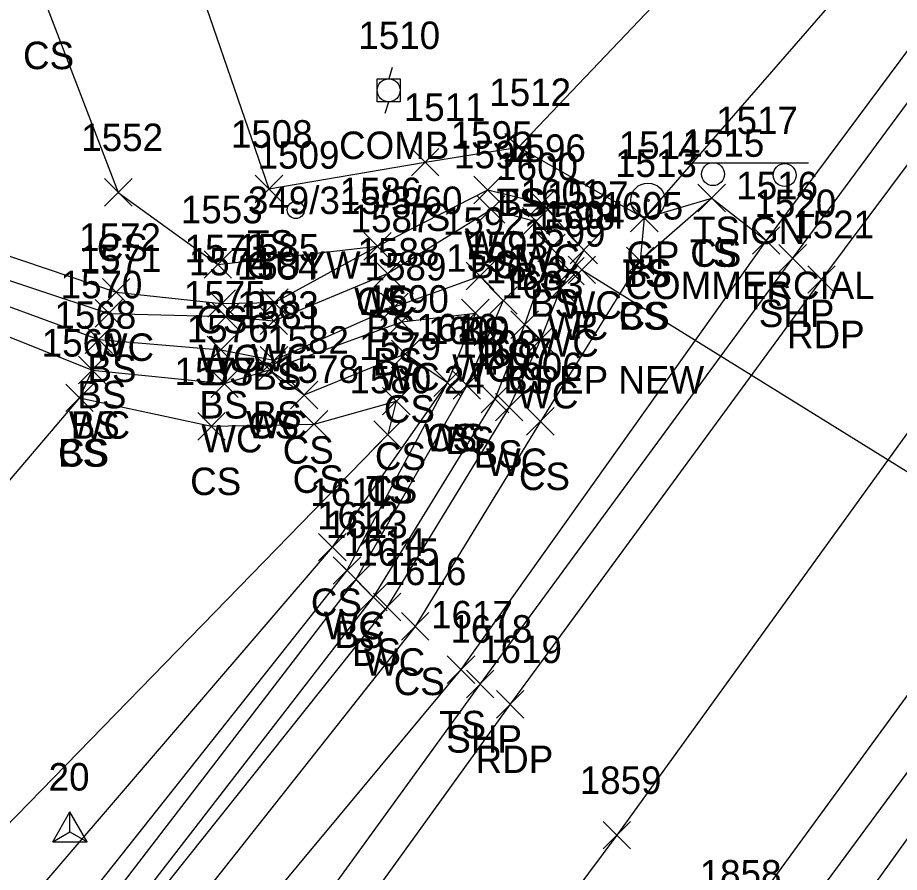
# Model space of a CAD drawing. Extents: x 1520648 to 1523413, y 732854 to 735518.
# Drawn here: x 1522326.3 to 1522390.5, y 734108.7 to 734170.9 of the extents above; entities that cross this region are included whole.
import ezdxf

# ---------------------------------------------------------------- set-up
doc = ezdxf.new("R2010")
doc.units = 0
for name, color, linetype in [('C_I', 7, 'Continuous'), ('CPSM', 7, 'Continuous'), ('D_A', 7, 'Continuous'), ('D_C', 7, 'Continuous'), ('D_I', 7, 'Continuous'), ('D_TIC', 7, 'Continuous'), ('DCP', 7, 'Continuous'), ('L_A', 7, 'Continuous'), ('L_I', 7, 'Continuous'), ('L_TIC', 7, 'Continuous'), ('LAWE', 7, 'Continuous'), ('LELB', 7, 'Continuous'), ('P_A', 7, 'Continuous'), ('P_I', 7, 'Continuous'), ('P_TIC', 7, 'Continuous'), ('PET', 7, 'Continuous'), ('PRC', 7, 'Continuous'), ('PSP', 7, 'Continuous'), ('R_A', 7, 'Continuous'), ('R_I', 7, 'Continuous'), ('RGP', 7, 'Continuous'), ('S_A', 7, 'Continuous'), ('S_C', 7, 'Continuous'), ('S_I', 7, 'Continuous'), ('SSGN', 7, 'Continuous'), ('U_A', 7, 'Continuous'), ('U_C', 7, 'Continuous'), ('U_I', 7, 'Continuous'), ('UP', 7, 'Continuous'), ('UPGW', 7, 'Continuous')]:
    doc.layers.add(name, color=color, linetype=linetype)

msp = doc.modelspace()

# ---------------------------------------------------------------- linework, layer by layer
at = {"layer": 'CPSM'}
for p, q in [((1522328.884, 734110.97), (1522330.134, 734113.135)), ((1522331.384, 734110.97), (1522330.134, 734113.135)), ((1522330.134, 734111.692), (1522330.134, 734113.135)), ((1522328.884, 734110.97), (1522330.134, 734111.692)), ((1522330.134, 734111.692), (1522330.134, 734111.692)), ((1522330.134, 734111.692), (1522331.384, 734110.97)), ((1522328.884, 734110.97), (1522331.384, 734110.97))]:
    msp.add_line(p, q, dxfattribs=at)
at = {"layer": 'D_TIC'}
for points in [[(1522366.367, 734151.564), (1522368.367, 734153.564)], [(1522368.367, 734151.564), (1522366.367, 734153.564)]]:
    msp.add_lwpolyline(points, dxfattribs=at)
at = {"layer": 'DCP'}
msp.add_lwpolyline([(1522367.367, 734152.564), (1522406.62, 734128.212)], dxfattribs=at)
at = {"layer": 'L_TIC'}
for points in [[(1522361.763, 734160.473), (1522363.763, 734162.473)], [(1522363.763, 734160.473), (1522361.763, 734162.473)], [(1522361.763, 734160.473), (1522363.763, 734162.473)], [(1522363.763, 734160.473), (1522361.763, 734162.473)], [(1522354.975, 734159.389), (1522356.975, 734161.389)], [(1522356.975, 734159.389), (1522354.975, 734161.389)], [(1522332.648, 734157.194), (1522334.648, 734159.194)], [(1522334.648, 734157.194), (1522332.648, 734159.194)], [(1522343.612, 734157.443), (1522345.612, 734159.443)], [(1522345.612, 734157.443), (1522343.612, 734159.443)], [(1522359.524, 734157.369), (1522361.524, 734159.369)], [(1522361.524, 734157.369), (1522359.524, 734159.369)], [(1522363.462, 734156.41), (1522365.462, 734158.41)], [(1522365.462, 734156.41), (1522363.462, 734158.41)], [(1522375.814, 734156.779), (1522377.814, 734158.779)], [(1522377.814, 734156.779), (1522375.814, 734158.779)], [(1522375.814, 734156.779), (1522377.814, 734158.779)], [(1522377.814, 734156.779), (1522375.814, 734158.779)], [(1522359.764, 734155.945), (1522361.764, 734157.945)], [(1522361.764, 734155.945), (1522359.764, 734157.945)], [(1522363.042, 734155.082), (1522365.042, 734157.082)], [(1522365.042, 734155.082), (1522363.042, 734157.082)], [(1522370.911, 734155.313), (1522372.911, 734157.313)], [(1522372.911, 734155.313), (1522370.911, 734157.313)], [(1522370.911, 734155.313), (1522372.911, 734157.313)], [(1522372.911, 734155.313), (1522370.911, 734157.313)], [(1522379.784, 734153.692), (1522381.784, 734155.692)], [(1522381.784, 734153.692), (1522379.784, 734155.692)], [(1522379.784, 734153.692), (1522381.784, 734155.692)], [(1522381.784, 734153.692), (1522379.784, 734155.692)], [(1522351.5, 734153.269), (1522353.5, 734155.269)], [(1522353.5, 734153.269), (1522351.5, 734155.269)], [(1522351.5, 734153.269), (1522353.5, 734155.269)], [(1522353.5, 734153.269), (1522351.5, 734155.269)], [(1522364.166, 734153.144), (1522366.166, 734155.144)], [(1522366.166, 734153.144), (1522364.166, 734155.144)], [(1522366.52, 734153), (1522368.52, 734155)], [(1522368.52, 734153), (1522366.52, 734155)], [(1522339.892, 734151.943), (1522341.892, 734153.943)], [(1522341.892, 734151.943), (1522339.892, 734153.943)], [(1522370.607, 734152.217), (1522372.607, 734154.217)], [(1522372.607, 734152.217), (1522370.607, 734154.217)], [(1522370.607, 734152.217), (1522372.607, 734154.217)], [(1522372.607, 734152.217), (1522370.607, 734154.217)], [(1522352.242, 734151.288), (1522354.242, 734153.288)], [(1522354.242, 734151.288), (1522352.242, 734153.288)], [(1522358.959, 734151.11), (1522360.959, 734153.11)], [(1522360.959, 734151.11), (1522358.959, 734153.11)], [(1522365.529, 734151.467), (1522367.529, 734153.467)], [(1522367.529, 734151.467), (1522365.529, 734153.467)], [(1522332.493, 734149.936), (1522334.493, 734151.936)], [(1522334.493, 734149.936), (1522332.493, 734151.936)], [(1522364.844, 734150.244), (1522366.844, 734152.244)], [(1522366.844, 734150.244), (1522364.844, 734152.244)], [(1522344.007, 734149.175), (1522346.007, 734151.175)], [(1522346.007, 734149.175), (1522344.007, 734151.175)], [(1522360.653, 734149.335), (1522362.653, 734151.335)], [(1522362.653, 734149.335), (1522360.653, 734151.335)], [(1522340.164, 734149.109), (1522342.164, 734151.109)], [(1522342.164, 734149.109), (1522340.164, 734151.109)], [(1522352.744, 734148.873), (1522354.744, 734150.873)], [(1522354.744, 734148.873), (1522352.744, 734150.873)], [(1522331.966, 734148.396), (1522333.966, 734150.396)], [(1522333.966, 734148.396), (1522331.966, 734150.396)], [(1522340.472, 734148.155), (1522342.472, 734150.155)], [(1522342.472, 734148.155), (1522340.472, 734150.155)], [(1522358.626, 734148.415), (1522360.626, 734150.415)], [(1522360.626, 734148.415), (1522358.626, 734150.415)], [(1522343.962, 734147.85), (1522345.962, 734149.85)], [(1522345.962, 734147.85), (1522343.962, 734149.85)], [(1522353.267, 734147.786), (1522355.267, 734149.786)], [(1522355.267, 734147.786), (1522353.267, 734149.786)], [(1522362.205, 734147.568), (1522364.205, 734149.568)], [(1522364.205, 734147.568), (1522362.205, 734149.568)], [(1522331.232, 734146.487), (1522333.232, 734148.487)], [(1522333.232, 734146.487), (1522331.232, 734148.487)], [(1522363.358, 734146.478), (1522365.358, 734148.478)], [(1522365.358, 734146.478), (1522363.358, 734148.478)], [(1522340.112, 734145.747), (1522342.112, 734147.747)], [(1522342.112, 734145.747), (1522340.112, 734147.747)], [(1522353.527, 734145.442), (1522355.527, 734147.442)], [(1522355.527, 734145.442), (1522353.527, 734147.442)], [(1522343.976, 734144.996), (1522345.976, 734146.996)], [(1522345.976, 734144.996), (1522343.976, 734146.996)], [(1522330.746, 734144.275), (1522332.746, 734146.275)], [(1522332.746, 734144.275), (1522330.746, 734146.275)], [(1522330.746, 734144.275), (1522332.746, 734146.275)], [(1522332.746, 734144.275), (1522330.746, 734146.275)], [(1522343.648, 734144.296), (1522345.648, 734146.296)], [(1522345.648, 734144.296), (1522343.648, 734146.296)], [(1522343.648, 734144.296), (1522345.648, 734146.296)], [(1522345.648, 734144.296), (1522343.648, 734146.296)], [(1522340.38, 734143.282), (1522342.38, 734145.282)], [(1522342.38, 734143.282), (1522340.38, 734145.282)], [(1522356.593, 734143.359), (1522358.593, 734145.359)], [(1522358.593, 734143.359), (1522356.593, 734145.359)], [(1522356.593, 734143.359), (1522358.593, 734145.359)], [(1522358.593, 734143.359), (1522356.593, 734145.359)], [(1522358.006, 734143.156), (1522360.006, 734145.156)], [(1522360.006, 734143.156), (1522358.006, 734145.156)], [(1522329.826, 734142.251), (1522331.826, 734144.251)], [(1522331.826, 734142.251), (1522329.826, 734144.251)], [(1522329.826, 734142.251), (1522331.826, 734144.251)], [(1522331.826, 734142.251), (1522329.826, 734144.251)], [(1522346.169, 734142.458), (1522348.169, 734144.458)], [(1522348.169, 734142.458), (1522346.169, 734144.458)], [(1522360.05, 734142.163), (1522362.05, 734144.163)], [(1522362.05, 734142.163), (1522360.05, 734144.163)], [(1522352.875, 734142.01), (1522354.875, 734144.01)], [(1522354.875, 734142.01), (1522352.875, 734144.01)], [(1522361.089, 734141.568), (1522363.089, 734143.568)], [(1522363.089, 734141.568), (1522361.089, 734143.568)], [(1522339.436, 734140.179), (1522341.436, 734142.179)], [(1522341.436, 734140.179), (1522339.436, 734142.179)], [(1522346.891, 734140.338), (1522348.891, 734142.338)], [(1522348.891, 734140.338), (1522346.891, 734142.338)], [(1522363.352, 734140.54), (1522365.352, 734142.54)], [(1522365.352, 734140.54), (1522363.352, 734142.54)], [(1522352.246, 734139.577), (1522354.246, 734141.577)], [(1522354.246, 734139.577), (1522352.246, 734141.577)], [(1522352.246, 734139.577), (1522354.246, 734141.577)], [(1522354.246, 734139.577), (1522352.246, 734141.577)], [(1522348.216, 734131.387), (1522350.216, 734133.387)], [(1522350.216, 734131.387), (1522348.216, 734133.387)], [(1522349.282, 734129.695), (1522351.282, 734131.695)], [(1522351.282, 734129.695), (1522349.282, 734131.695)], [(1522349.925, 734129.052), (1522351.925, 734131.052)], [(1522351.925, 734129.052), (1522349.925, 734131.052)], [(1522351.202, 734127.759), (1522353.202, 734129.759)], [(1522353.202, 734127.759), (1522351.202, 734129.759)], [(1522352.212, 734127.042), (1522354.212, 734129.042)], [(1522354.212, 734127.042), (1522352.212, 734129.042)], [(1522354.247, 734125.63), (1522356.247, 734127.63)], [(1522356.247, 734125.63), (1522354.247, 734127.63)], [(1522357.576, 734122.488), (1522359.576, 734124.488)], [(1522359.576, 734122.488), (1522357.576, 734124.488)]]:
    msp.add_lwpolyline(points, dxfattribs=at)
at = {"layer": 'LAWE'}
for points in [[(1522250.491, 734235.037), (1522272.418, 734218.931), (1522297.866, 734198.743), (1522307.579, 734174.196), (1522311.425, 734163.768), (1522313.948, 734156.23), (1522320.922, 734149.602), (1522331.746, 734145.275), (1522341.38, 734144.282), (1522344.648, 734145.296), (1522354.267, 734148.786), (1522359.626, 734149.415), (1522357.593, 734144.359), (1522350.282, 734130.695), (1522326.677, 734100.964), (1522300.85, 734070.206), (1522283.214, 734045.187), (1522247.826, 734003.159), (1522235.935, 733986.962), (1522232.503, 733982.111), (1522233.889, 733977.864), (1522237.924, 733975.081)], [(1522275.07, 734222.651), (1522300.966, 734201.77), (1522314.292, 734178.563), (1522316.721, 734163.79), (1522318.9, 734158.493), (1522323.207, 734154.41), (1522333.493, 734150.936), (1522341.164, 734150.109), (1522345.007, 734150.175), (1522352.5, 734154.269), (1522360.524, 734158.369), (1522364.462, 734157.41), (1522367.52, 734154), (1522366.529, 734152.467), (1522365.844, 734151.244), (1522364.358, 734147.478), (1522362.089, 734142.568), (1522353.212, 734128.042), (1522330.191, 734099.187)]]:
    msp.add_lwpolyline(points, dxfattribs=at)
at = {"layer": 'LELB'}
for points in [[(1522395.09, 734350.531), (1522415.249, 734331.589), (1522444.221, 734311.426), (1522451.406, 734298.653), (1522468.172, 734280.372), (1522463.007, 734272.968), (1522457.879, 734264.636), (1522425.472, 734222.776), (1522401.641, 734190.495), (1522371.911, 734156.313), (1522371.607, 734153.217)], [(1522384.486, 734338.491), (1522408.872, 734322.629), (1522444.221, 734311.426), (1522437.111, 734272.849), (1522404.016, 734240.219), (1522381.491, 734204.71), (1522358.627, 734188.026), (1522348.686, 734185.071), (1522337.789, 734178.249), (1522344.612, 734158.443), (1522355.975, 734160.389), (1522362.763, 734161.473), (1522371.911, 734156.313), (1522376.814, 734157.779), (1522380.784, 734154.692)], [(1522457.968, 734316.512), (1522465.357, 734303.49), (1522470.912, 734292.363), (1522471.732, 734284.064), (1522466.061, 734271.742), (1522460.873, 734262.705), (1522429.298, 734219.625), (1522405.436, 734187.852), (1522380.784, 734154.692), (1522358.576, 734123.488), (1522334.875, 734095.049), (1522309.576, 734064.854), (1522289.905, 734038.9), (1522256.583, 733995.71), (1522247.93, 733981.241), (1522246.394, 733977.736)], [(1522468.172, 734280.372), (1522452.702, 734267.117), (1522413.12, 734232.572), (1522394.839, 734195.166), (1522362.763, 734161.473)], [(1522254.626, 734242.445), (1522277.101, 734224.581), (1522303.246, 734203.728), (1522319.969, 734183.489), (1522328.279, 734172.152), (1522333.648, 734158.194), (1522340.892, 734152.943), (1522352.5, 734154.269)], [(1522251.119, 734236.06), (1522272.787, 734219.747), (1522299.135, 734200.043), (1522308.726, 734174.595), (1522312.876, 734163.824), (1522314.782, 734156.547), (1522320.994, 734151.619), (1522332.232, 734147.487), (1522341.112, 734146.747), (1522344.976, 734145.996), (1522353.744, 734149.873), (1522359.959, 734152.11), (1522361.653, 734150.335), (1522359.006, 734144.156), (1522350.925, 734130.052), (1522328.139, 734100.37), (1522301.957, 734069.708), (1522284.253, 734044.067), (1522248.494, 734002.647), (1522236.848, 733986.418), (1522234.99, 733978.889), (1522237.802, 733975.956)], [(1522274.399, 734221.594), (1522300.475, 734201.321), (1522311.683, 734176.782), (1522315.629, 734163.723), (1522317.176, 734158.113), (1522321.908, 734153.037), (1522332.966, 734149.396), (1522341.472, 734149.155), (1522344.962, 734148.85), (1522353.242, 734152.288), (1522360.764, 734156.945), (1522364.042, 734156.082), (1522365.166, 734154.144), (1522363.205, 734148.568), (1522361.05, 734143.163), (1522352.202, 734128.759), (1522329.533, 734099.474)], [(1522376.814, 734157.779), (1522371.607, 734153.217), (1522364.352, 734141.54), (1522355.247, 734126.63), (1522332.08, 734097.329), (1522306.782, 734066.944), (1522288.152, 734040.883), (1522253.165, 733999.02), (1522246.652, 733983.966), (1522243.698, 733979.269)], [(1522344.648, 734145.296), (1522347.169, 734143.458), (1522354.527, 734146.442), (1522357.593, 734144.359), (1522349.216, 734132.387), (1522324.183, 734103.261), (1522298.736, 734071.29), (1522282.293, 734046.597), (1522246.807, 734004.076), (1522231.674, 733985.079), (1522222.698, 733979.344)], [(1522331.746, 734145.275), (1522330.826, 734143.251), (1522307.65, 734116.035), (1522282.293, 734082.141), (1522263.448, 734058.684), (1522234.48, 734027.828), (1522226.547, 734014.571), (1522216.683, 733985.084), (1522201.997, 733964.193)], [(1522330.826, 734143.251), (1522340.436, 734141.179), (1522347.891, 734141.338), (1522353.875, 734143.01), (1522353.246, 734140.577)], [(1522353.246, 734140.577), (1522319.919, 734106.375), (1522293, 734074.596), (1522275.622, 734051.294), (1522244.544, 734005.967), (1522222.698, 733979.344), (1522201.997, 733964.193), (1522167.916, 733938.992), (1522145.374, 733925.913), (1522137.653, 733917.419), (1522137.34, 733905.336), (1522137.089, 733900.599)], [(1522399.215, 734122.541), (1522383.71, 734100.994), (1522356.243, 734060.921), (1522336.346, 734027.129), (1522331.321, 734016.253), (1522299.589, 733987.369), (1522286.663, 733965.177), (1522279.32, 733956.929)]]:
    msp.add_lwpolyline(points, dxfattribs=at)
at = {"layer": 'P_TIC'}
for points in [[(1522381.703, 734152.399), (1522383.703, 734154.399)], [(1522383.703, 734152.399), (1522381.703, 734154.399)], [(1522383.803, 734150.862), (1522385.803, 734152.862)], [(1522385.803, 734150.862), (1522383.803, 734152.862)], [(1522358.979, 734121.447), (1522360.979, 734123.447)], [(1522360.979, 734121.447), (1522358.979, 734123.447)], [(1522361.154, 734119.963), (1522363.154, 734121.963)], [(1522363.154, 734119.963), (1522361.154, 734121.963)], [(1522368.918, 734110.445), (1522370.918, 734112.445)], [(1522370.918, 734110.445), (1522368.918, 734112.445)]]:
    msp.add_lwpolyline(points, dxfattribs=at)
at = {"layer": 'PET'}
for points in [[(1522409.889, 734185.458), (1522384.803, 734151.862), (1522362.154, 734120.963), (1522340.089, 734090.379), (1522317.27, 734060.024), (1522297.221, 734033.868), (1522262.688, 733990.171), (1522247.435, 733972.23), (1522223.908, 733946.238), (1522192.475, 733913.956), (1522164.522, 733888.054), (1522124.702, 733855.724), (1522089.977, 733831.334), (1522050.332, 733806.095), (1522008.227, 733782.155), (1521961.733, 733759.371), (1521937.846, 733748.917), (1521892.742, 733731.021), (1521853.037, 733716.934), (1521810.117, 733704.128), (1521784.901, 733696.796), (1521738.039, 733684.332), (1521683.498, 733669.737)], [(1522405.747, 734141.77), (1522378.634, 734104.64), (1522350.274, 734066.93), (1522320.645, 734027.193), (1522293.194, 733992.175), (1522263.712, 733955.946)]]:
    msp.add_lwpolyline(points, dxfattribs=at)
at = {"layer": 'PRC'}
msp.add_lwpolyline([(1522396.734, 734148.567), (1522369.918, 734111.445), (1522340.214, 734071.61), (1522312.59, 734035.113), (1522285.537, 734000.452), (1522254.708, 733962.62), (1522224.204, 733928.998)], dxfattribs=at)
at = {"layer": 'PSP'}
for points in [[(1522407.438, 734186.957), (1522382.703, 734153.399), (1522359.979, 734122.447), (1522337.917, 734092.022), (1522315.008, 734061.409), (1522295.214, 734035.758), (1522260.619, 733991.788), (1522245.877, 733973.988), (1522222.051, 733948.064), (1522190.446, 733915.418), (1522160.989, 733888.489), (1522154.255, 733883.337), (1522127.344, 733861.553), (1522088.304, 733833.578), (1522048.983, 733808.783), (1522007.27, 733785.063), (1521960.899, 733762.469), (1521936.677, 733751.076), (1521891.961, 733733.483), (1521851.863, 733719.561), (1521809.017, 733706.622), (1521784.101, 733699.987), (1521736.058, 733688.523), (1521682.585, 733672.906)], [(1522408.205, 734139.279), (1522381.044, 734102.475), (1522353.021, 734064.874), (1522324.006, 734025.281), (1522296.174, 733989.549), (1522266.628, 733953.31), (1522235.292, 733918.787), (1522209.781, 733890.984), (1522201.901, 733884.12), (1522173.488, 733859.111), (1522154.026, 733843.415), (1522113.548, 733816.073), (1522079.344, 733793.188), (1522048.296, 733774.459), (1522016.588, 733757.423), (1521993.944, 733745.829), (1521965.161, 733732.44), (1521948.662, 733724.972), (1521904.277, 733707.61), (1521888.633, 733701.989), (1521847.287, 733686.723), (1521809.288, 733673.666)]]:
    msp.add_lwpolyline(points, dxfattribs=at)
at = {"layer": 'RGP'}
msp.add_line((1522372.173, 734157.622), (1522372.173, 734157.622), dxfattribs=at)
for radius in [1.25, 0.0833]:
    msp.add_circle((1522372.173, 734157.622), radius, dxfattribs=at)
at = {"layer": 'SSGN'}
for p, q in [((1522375.25, 734160.352), (1522383.848, 734160.352)), ((1522379.273, 734159.448), (1522379.273, 734159.448))]:
    msp.add_line(p, q, dxfattribs=at)
for centre in [(1522376.912, 734159.519), (1522382.126, 734159.448)]:
    msp.add_circle(centre, 0.833, dxfattribs=at)
at = {"layer": 'UP'}
for p, q in [((1522353.572, 734167.283), (1522353.322, 734166.45)), ((1522352.489, 734164.783), (1522352.489, 734166.45)), ((1522352.489, 734166.45), (1522354.155, 734166.45)), ((1522354.155, 734166.45), (1522354.155, 734164.783)), ((1522353.322, 734165.616), (1522353.322, 734165.616)), ((1522354.155, 734164.783), (1522352.489, 734164.783)), ((1522353.072, 734163.95), (1522353.322, 734164.783))]:
    msp.add_line(p, q, dxfattribs=at)
msp.add_circle((1522353.322, 734165.616), 0.833, dxfattribs=at)
at = {"layer": 'UPGW'}
for radius in [0.625, 0.0833]:
    msp.add_circle((1522346.566, 734156.913), radius, dxfattribs=at)

# ---------------------------------------------------------------- texts
at = {"layer": 'C_I'}
msp.add_text('20', height=2, dxfattribs=at).set_placement((1522328.583, 734114.692))
at = {"layer": 'D_A'}
msp.add_text('P', height=2, dxfattribs=at).set_placement((1522366.745, 734147.564))
at = {"layer": 'D_C'}
msp.add_text('24" CPEP NEW', height=2, dxfattribs=at).set_placement((1522357.336, 734143.564))
at = {"layer": 'D_I'}
msp.add_text('1604', height=2, dxfattribs=at).set_placement((1522364.548, 734155.564))
at = {"layer": 'L_A'}
for s, p in [('CS', (1522326.72, 734167.152)), ('TS', (1522361.173, 734156.473)), ('BS', (1522361.204, 734156.473)), ('TS', (1522354.384, 734155.389)), ('CS', (1522332.089, 734153.194)), ('TS', (1522343.021, 734153.443)), ('WC', (1522358.832, 734153.369)), ('WC', (1522362.769, 734152.41)), ('TS', (1522375.223, 734152.779)), ('CS', (1522375.255, 734152.779)), ('BS', (1522359.205, 734151.945)), ('BS', (1522362.483, 734151.082)), ('TS', (1522370.32, 734151.313)), ('BS', (1522370.352, 734151.313)), ('WC', (1522350.807, 734149.269)), ('CS', (1522350.941, 734149.269)), ('BS', (1522363.607, 734149.144)), ('TS', (1522379.194, 734149.692)), ('TS', (1522379.194, 734149.692)), ('WC', (1522365.827, 734149)), ('CS', (1522339.332, 734147.943)), ('CS', (1522370.048, 734148.217)), ('BS', (1522370.048, 734148.217)), ('BS', (1522351.683, 734147.288)), ('WC', (1522364.836, 734147.467)), ('BS', (1522358.4, 734147.11)), ('WC', (1522331.8, 734145.936)), ('WC', (1522364.151, 734146.244)), ('BS', (1522360.094, 734145.335)), ('WC', (1522339.472, 734145.109)), ('WC', (1522343.314, 734145.175)), ('BS', (1522352.185, 734144.873)), ('BS', (1522331.407, 734144.396)), ('BS', (1522339.913, 734144.155)), ('WC', (1522357.933, 734144.415)), ('BS', (1522343.403, 734143.85)), ('WC', (1522352.574, 734143.786)), ('BS', (1522361.646, 734143.568)), ('BS', (1522330.673, 734142.487)), ('WC', (1522362.665, 734142.478)), ('BS', (1522339.552, 734141.747)), ('CS', (1522352.968, 734141.442)), ('BS', (1522343.417, 734140.996)), ('WC', (1522330.053, 734140.275)), ('BS', (1522330.187, 734140.275)), ('WC', (1522342.955, 734140.296)), ('CS', (1522343.089, 734140.296)), ('WC', (1522339.688, 734139.282)), ('WC', (1522355.9, 734139.359)), ('CS', (1522356.034, 734139.359)), ('BS', (1522357.447, 734139.156)), ('CS', (1522329.267, 734138.251)), ('BS', (1522329.267, 734138.251)), ('CS', (1522345.61, 734138.458)), ('CS', (1522352.316, 734138.01)), ('BS', (1522359.491, 734138.163)), ('WC', (1522360.396, 734137.568)), ('CS', (1522346.332, 734136.338)), ('CS', (1522362.793, 734136.54)), ('CS', (1522338.877, 734136.179)), ('TS', (1522351.656, 734135.577)), ('CS', (1522351.687, 734135.577)), ('CS', (1522347.657, 734127.387)), ('WC', (1522348.589, 734125.695)), ('BS', (1522349.366, 734125.052)), ('BS', (1522350.643, 734123.759)), ('WC', (1522351.519, 734123.042)), ('CS', (1522353.688, 734121.63)), ('TS', (1522356.986, 734118.488))]:
    msp.add_text(s, height=2, dxfattribs=at).set_placement(p)
at = {"layer": 'L_I'}
for s, p in [('1512', (1522360.637, 734164.473)), ('1512', (1522360.637, 734164.473)), ('1511', (1522354.416, 734163.389)), ('1508', (1522341.84, 734161.443)), ('1595', (1522357.832, 734161.369)), ('1552', (1522330.955, 734161.194)), ('1515', (1522374.688, 734160.779)), ('1515', (1522374.688, 734160.779)), ('1596', (1522361.714, 734160.41)), ('1594', (1522358.071, 734159.945)), ('1600', (1522361.137, 734159.082)), ('1513', (1522369.785, 734159.313)), ('1513', (1522369.785, 734159.313)), ('1516', (1522378.603, 734157.692)), ('1516', (1522378.603, 734157.692)), ('1586', (1522349.752, 734157.269)), ('1586', (1522349.752, 734157.269)), ('1601', (1522362.914, 734157.144)), ('1597', (1522364.827, 734157)), ('1605', (1522368.788, 734156.217)), ('1605', (1522368.788, 734156.217)), ('1553', (1522338.199, 734155.943)), ('1587', (1522350.549, 734155.288)), ('1592', (1522357.266, 734155.11)), ('1598', (1522363.836, 734155.467)), ('1572', (1522330.8, 734153.936)), ('1599', (1522363.143, 734154.244)), ('1573', (1522338.472, 734153.109)), ('1585', (1522342.314, 734153.175)), ('1593', (1522358.961, 734153.335)), ('1571', (1522330.84, 734152.396)), ('1588', (1522351.052, 734152.873)), ('1591', (1522357.5, 734152.415)), ('1574', (1522338.779, 734152.155)), ('1584', (1522342.269, 734151.85)), ('1589', (1522351.567, 734151.786)), ('1602', (1522360.386, 734151.568)), ('1570', (1522329.453, 734150.487)), ('1603', (1522361.539, 734150.478)), ('1575', (1522338.419, 734149.747)), ('1590', (1522351.748, 734149.442)), ('1583', (1522342.284, 734148.996)), ('1568', (1522329.005, 734148.275)), ('1568', (1522329.005, 734148.275)), ('1581', (1522342.522, 734148.296)), ('1581', (1522342.522, 734148.296)), ('1576', (1522338.632, 734147.282)), ('1610', (1522355.333, 734147.359)), ('1610', (1522355.333, 734147.359)), ('1609', (1522356.179, 734147.156)), ('1569', (1522328.078, 734146.251)), ('1569', (1522328.078, 734146.251)), ('1582', (1522344.476, 734146.458)), ('1579', (1522351.175, 734146.01)), ('1608', (1522358.231, 734146.163)), ('1607', (1522359.27, 734145.568)), ('1577', (1522337.743, 734144.179)), ('1578', (1522345.198, 734144.338)), ('1606', (1522361.478, 734144.54)), ('1580', (1522350.467, 734143.577)), ('1580', (1522350.467, 734143.577)), ('1611', (1522347.61, 734135.387)), ('1612', (1522348.108, 734133.695)), ('1613', (1522348.752, 734133.052)), ('1614', (1522350.028, 734131.759)), ('1615', (1522351.038, 734131.042)), ('1616', (1522353.018, 734129.63)), ('1617', (1522356.403, 734126.488))]:
    msp.add_text(s, height=2, dxfattribs=at).set_placement(p)
at = {"layer": 'P_A'}
for s, p in [('SHP', (1522380.239, 734148.399)), ('RDP', (1522382.291, 734146.862)), ('SHP', (1522357.515, 734117.447)), ('RDP', (1522359.643, 734115.963))]:
    msp.add_text(s, height=2, dxfattribs=at).set_placement(p)
at = {"layer": 'P_I'}
for s, p in [('1520', (1522379.924, 734156.399)), ('1521', (1522382.677, 734154.862)), ('1618', (1522357.806, 734125.447)), ('1619', (1522359.973, 734123.963)), ('1859', (1522367.217, 734114.445)), ('1858', (1522375.941, 734107.64))]:
    msp.add_text(s, height=2, dxfattribs=at).set_placement(p)
at = {"layer": 'R_A'}
msp.add_text('GP', height=2, dxfattribs=at).set_placement((1522370.606, 734152.622))
at = {"layer": 'R_I'}
msp.add_text('1514', height=2, dxfattribs=at).set_placement((1522370.047, 734160.622))
at = {"layer": 'S_A'}
msp.add_text('TSIGN', height=2, dxfattribs=at).set_placement((1522375.448, 734154.431))
at = {"layer": 'S_C'}
msp.add_text('COMMERCIAL', height=2, dxfattribs=at).set_placement((1522370.543, 734150.431))
at = {"layer": 'S_I'}
msp.add_text('1517', height=2, dxfattribs=at).set_placement((1522377.141, 734162.431))
at = {"layer": 'U_A'}
for s, p in [('COMB', (1522349.708, 734160.616)), ('GUYW', (1522342.96, 734151.913))]:
    msp.add_text(s, height=2, dxfattribs=at).set_placement(p)
at = {"layer": 'U_C'}
msp.add_text('349/315/3/60', height=2, dxfattribs=at).set_placement((1522343.078, 734156.616))
at = {"layer": 'U_I'}
for s, p in [('1510', (1522351.109, 734168.616)), ('1509', (1522343.787, 734159.913))]:
    msp.add_text(s, height=2, dxfattribs=at).set_placement(p)

doc.saveas('drawing.dxf')
